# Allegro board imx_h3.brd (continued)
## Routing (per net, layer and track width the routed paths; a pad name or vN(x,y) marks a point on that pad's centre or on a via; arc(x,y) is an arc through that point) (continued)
VBUS_MODEM: length 8.2
  TOP w0.5: C237.1 82.73,13.85 83.13,14.25 83.13,15.87 83.07,15.93 v1(83.07,15.94)
  BOTTOM w0.3: 83.64,12.96 83.65,12.97 83.65,14.3 83.24,14.71 C238.1 ; L24.1 82.59,16.41 83.32,15.68 83.32,15.34
  BOTTOM w0.5: v1(83.07,15.94) 83.06,15.93 83.06,15.6 83.32,15.34 83.32,15.3 C238.1
VBUS_OTG: length 49.7
  TOP w0.1: 84.74,8.47 C236.1 85.91,7.62 ; D4.C 85.22,10.47 ; D4.C 86,9.81 ; D4.C 84.43,9.81 ; C241.1 84.69,6.13 ; C241.1 84.22,6.6 ; C241.1 84.22,5.66
  TOP w0.3: v1(106.34,73.15) 106.32,73.16 R93.2 105.49,73.4 104.9,73.99 104.06,73.99 103.97,74.08 103.97,74.56 C254.1 ; v1(115.6,15.2) L3.1
  TOP w0.5: v1(84.32,5.35) 84.74,5.78 C236.1 85.22,8.1 D4.C
  PWR w0.5: 103.79,42.12 103.79,42.61 101.64,44.75 101.64,46.9 103.11,48.37 103.11,50.81 104.68,52.38 104.68,55.97 104.42,56.22 v1(104.42,62.53)
  BOTTOM w0.5: v1(104.42,62.53) 104.41,62.53 103.62,63.31 103.62,70.66 106.11,73.15 v1(106.34,73.15)
  vias: v1(84.47,4.25) v1(85.14,5.22) v1(85.27,4.27) v1(85.92,5.27) v1(86.02,4.27) v1(120.2,31.22) v1(122.63,31.19)
VBUS_TOP: length 7.9
  TOP w0.1: C240.1 27.52,22.7 27.65,22.82 v1(27.65,23.15)
  TOP w0.3: C234.1 26.35,21.2 C240.1
  BOTTOM w0.3: v1(27.65,23.15) 27.65,23.65 27.35,23.94 26.65,23.94
  BOTTOM w0.5: L21.1 28.8,20.27 28.8,22 v1(27.65,23.15)
VDD1P5_1V5: length 11.9
  TOP w0.5: 64.48,39.52 65.58,39.52 C121.1 ; 64.48,39.52 64.57,39.43 64.57,39.36 64.92,39.02 64.92,38.89 C119.1 65.66,38.76 66.27,38.16 66.27,37.74 C123.1 ; 64.48,39.52 64.41,39.59 v1(64.41,39.64)
  PWR w0.5: v1(64.41,39.64) 64.47,39.64 64.67,39.84 64.67,41.48 64.33,41.81 64.25,41.81 63.65,42.42 63.48,42.42 62.59,43.31 v1(62.59,43.23)
  BOTTOM w0.25: U1.D16 62.59,43.29 v1(62.59,43.23)
  BOTTOM w0.5: C122.1 64.6,39.99 64.6,39.88 64.41,39.69 v1(64.41,39.64) 64.53,39.52 64.63,39.52 C120.1
VDD_1V5: length 6.5
  TOP w0.1: 101.63,82.64 101.63,83.64
  TOP w0.3: 101.63,83.64 101.52,83.75 100.38,83.75 100.23,83.89 100.23,84.94 100.44,85.14 100.92,85.14 101.38,85.61 101.38,86.22 v1(101.46,86.3)
  BOTTOM w0.3: v1(101.46,86.3) 101.39,86.23 101.39,85.52
VDD_4P2: length 19.3
  TOP w0.1: C129.1 65.72,32.75 65.73,32.75 ; C129.1 65.71,32.29 ; C129.1 65.24,32.75
  TOP w0.5: 64.28,33.94 64.28,32.85 C131.1 64.38,32.75 65.73,32.75 ; 64.28,33.94 64.28,33.52 v1(65.06,32.74) ; 64.28,33.94 C132.1 64.3,34.29 64.3,34.72 64.07,34.94 64.07,35.02 63.93,35.16 63.84,35.16 63.53,35.48 C130.1 63.24,35.61 62.68,36.17 v1(61.65,36.17)
  BOTTOM w0.3: 59.84,41.24 59.84,40.27 59.54,39.97 59.54,39.89 59.42,39.77 59.42,38.72 59.84,38.3 59.84,37.53 61.09,36.29 61.52,36.29 v1(61.65,36.17)
  BOTTOM w0.5: v1(65.06,32.74) 68.41,32.74 C133.1
VDD_XTAL: length 56.7
  TOP w0.1: C140.1 58.39,41.47 58.39,41.18 58.22,41.01 58.22,40.45 58.22,40.45 58.22,40.11 58.43,39.9 58.48,39.9 58.82,39.56 58.82,38.88 58.42,38.48 58.42,37.98 58.41,37.97 58.41,33.31 57.98,32.88 57.98,29.86 60.73,27.11 61.7,27.11 61.84,26.96 v1(61.84,26.76) ; v1(69.64,20.32) 69.64,20.34 69.31,20.68 65.34,20.68 65.05,20.38 64.82,20.15 64.8,20.15 63.62,18.97 63.62,3.19 SW2.2
  TOP w0.3: v1(58.66,42.47) 58.66,42.32 58.73,42.25 C140.1
  BOTTOM w0.1: v1(69.64,20.32) 69.55,20.32 68.75,21.12 65.99,21.12 61.84,25.26 v1(61.84,26.76)
  BOTTOM w0.3: v1(58.66,42.47) 58.66,42.47 58.68,42.47 59.05,42.84
ADC_BATT: length 22.7
  TOP w0.1: v1(61.87,43.17) 61.89,43.17 62.23,42.83 63.29,42.83 63.41,42.71 64.2,42.71 64.31,42.81 64.42,42.81 64.58,42.98 64.58,42.99 64.91,43.32 66.43,43.32 66.8,42.94 74.09,42.94 75.48,44.34 76.07,44.34 76.56,43.85 76.56,42.2 75.25,40.89 v1(74.6,40.89)
  BOTTOM w0.1: C153.1 73.53,40.09 R165.2 74.33,40.89 v1(74.6,40.89) ; v1(61.87,43.17) 61.83,43.13 61.81,43.13 61.52,42.84 61.45,42.84
BKGD: length 15
  TOP w0.1: 13.21,57.57 13.21,59.47 13.64,59.9 15.79,59.9 16.69,60.79 16.69,64.56 17.43,65.31 18.98,65.31 v1(19.45,65.78)
  BOTTOM w0.1: v1(19.45,65.78) 19.45,66.98 19.16,67.28 U4.34
BT_ACTIVE: length 116.3
  TOP w0.1: v1(12.87,32.44) 12.93,32.5 J20.41
  INT1 w0.1: v1(12.87,32.44) 12.94,32.51 12.94,40.36 12.96,40.38 12.96,40.97 20.16,48.17 20.16,49.57 21.37,50.78 21.37,51.87 21.36,51.87 21.36,52.21 22.31,53.15 22.82,53.15 23.15,53.15 23.48,53.15 27.39,53.15 28.6,54.37 28.97,54.37 30.31,55.71 30.31,55.71 31.57,56.97 31.91,56.97 32.24,56.97 32.24,56.97 32.91,56.97 32.92,56.96 33.75,56.96 33.77,56.97 34.26,56.97 34.26,56.97 34.84,56.97 34.85,56.96 35.34,56.96 35.91,56.96 36.96,58.01 36.96,64.3 44.75,72.09 45.94,72.09 46.34,72.5 62.85,72.5 71.41,72.5 71.85,72.05 79,72.05 79.45,72.5 80.47,72.5 83.03,75.06 83.03,78.06 84.03,79.06 85.96,79.06 v1(86.05,79.14)
  BOTTOM w0.1: v1(86.05,79.14) 86.6,79.69 86.6,81.39 88.59,83.37 88.59,83.73 88.8,83.94 R101.1
BT_HOST_WAKE: length 86.1
  TOP w0.1: J20.43 14.55,31.7 14.54,31.69 14.52,31.69 14.51,31.7 14.21,31.7 14.2,31.69 v1(12.92,31.69)
  INT1 w0.1: v1(47.75,71.78) 44.72,71.78 37.16,64.22 37.16,57.93 35.99,56.76 35.26,56.76 34.77,56.76 34.76,56.77 34.17,56.77 34.17,56.78 33.85,56.78 33.84,56.76 32.84,56.76 32.83,56.76 32.16,56.76 32.16,56.77 31.66,56.77 30.4,55.51 30.39,55.51 29.05,54.17 28.68,54.17 27.47,52.95 23.4,52.95 22.39,52.95 21.56,52.12 21.56,51.72 21.57,51.72 21.57,50.7 20.36,49.49 20.36,48.09 13.16,40.89 13.16,32.91 13.27,32.79 13.27,32.08 12.92,31.73 v1(12.92,31.69)
  BOTTOM w0.1: U17.13 63.9,65.74 61.71,67.93 61.71,70.19 61.08,70.83 59.71,72.2 59.39,72.2 59.39,72.2 48.52,72.2 48.09,71.78 v1(47.75,71.78)
BT_RESET_B: length 79.2
  TOP w0.1: v1(19.44,38.32) 20.8,36.96 20.8,36.16 22.11,34.85 22.11,32.45 22.46,32.1 J20.42
  INT1 w0.1: v1(45.59,70.79) 45.59,70.75 44.44,69.61 44.44,68.99 43.7,68.26 43.7,67.76 43.7,67.76 43.7,66.67 38.15,61.11 38.15,57.91 37.69,57.46 37.69,57.45 36.41,56.16 36.02,56.16 35.69,56.16 35.36,56.16 35.01,56.16 34.52,56.16 34.51,56.17 34.1,56.17 34.09,56.16 32.58,56.16 32.58,56.16 32.08,56.16 32.08,56.16 31.91,56.16 30.65,54.91 30.64,54.91 29.3,53.56 28.93,53.56 25.96,50.6 25.96,46.32 21.71,42.06 21.71,40.08 19.94,38.32 v1(19.44,38.32)
  BOTTOM w0.1: U17.16 63.41,67.24 62.41,68.24 62.41,70.35 61.88,70.88 61.58,71.18 61.56,71.2 59.96,72.8 59.65,72.8 59.65,72.8 47.37,72.8 47.34,72.81 47.16,72.81 45.59,71.24 v1(45.59,70.79)
BUTTON_1: length 148.3
  TOP w0.1: R151.1 106.13,100.6 R127.1 106.17,100.46 v1(106.17,99.61)
  INT1 w0.1: v1(58.4,25.63) 58.45,25.63 59.65,24.43 60.98,24.43 61.75,23.66 83.15,23.66 83.76,23.06 83.76,23.06 83.87,22.94 88.52,22.94 88.72,23.14 v1(88.72,23.24) ; v1(106.17,99.61) 106.17,99.39 107.23,98.33 107.23,80.88 104.14,77.78 104.14,71.86 102.86,70.59 102.86,62.19 103.59,61.46 103.59,59.16 94.72,50.28 v1(94.72,44.95)
  BOTTOM w0.1: 53.45,42.03 53.42,42.03 53.06,41.68 52.66,41.68 52.15,41.17 52.15,41.11 51.97,40.93 51.97,40.93 50.81,39.78 49.61,39.78 48.72,38.89 48.33,38.89 47.55,38.11 47.55,35.81 48.79,34.56 49.23,34.56 50.74,33.04 51.07,33.04 54.94,29.16 55.64,29.16 58.4,26.4 v1(58.4,25.63) ; v1(88.72,23.24) 88.72,24.57 89.09,24.95 89.09,34.66 91.22,36.78 93.37,36.78 94.13,37.54 94.14,37.54 94.52,37.91 94.52,39.55 96.81,41.83 97,41.83 97.25,42.08 97.25,43.45 95.65,45.05 94.82,45.05 v1(94.72,44.95)
BUTTON_2: length 69.9
  TOP w0.1: v1(52.96,42.43) 52.92,42.43 50.8,40.31 49.32,40.31 48.99,39.97 v1(48.99,39.94) 48.99,39.91 48.28,39.21 R124.1 ; R144.1 88.69,7.97 87.75,8.91 87.75,13.29 83.16,17.88 83.16,18.65 80.51,21.29 64.09,21.29 63.15,20.35 60.67,20.35 53.99,27.03 53.98,27.03 53.74,27.26 53.74,27.28 49.06,31.97 49.06,33.78 49.05,33.79 v1(49.06,33.79)
  BOTTOM w0.1: 53.45,42.84 53.04,42.43 v1(52.96,42.43) ; v1(48.99,39.94) 48.8,39.94 47.63,38.77 47.63,38.76 47.14,38.28 47.14,36.62 47.14,36.61 47.14,36.28 47.14,36.27 47.14,35.8 49.06,33.88 v1(49.06,33.79)
BUTTON_3: length 85.6
  TOP w0.1: v1(42.44,40.48) 42.66,40.71 46.73,40.71 ; v1(53.1,43.24) 53.1,43.21 52.74,42.85 51.49,42.85 50.38,41.74 48.81,41.74 47.77,40.71 46.73,40.71 ; R140.1 46.6,40.58 46.73,40.71 ; v1(97.9,7.7) 98.33,7.27 R153.2
  INT1 w0.1: v1(97.9,7.7) 97.74,7.86 95.06,7.86 94.97,7.94 94.97,7.97 94.82,7.97 94.59,8.2 93.91,8.2 91.84,10.27 91.84,12.12 81.84,22.12 81.73,22.12 69.14,22.12 68.2,23.06 62,23.06 61.99,23.06 61.5,23.06 61.26,23.29 61.26,23.29 60.78,23.77 59.1,23.77 57.33,25.54 57.33,25.78 57.23,25.88 v1(56.1,25.88)
  BOTTOM w0.1: v1(53.1,43.24) 53.11,43.25 53.11,43.3 53.45,43.63 ; v1(42.44,40.48) 42.53,40.39 42.53,38.59 42.69,38.44 42.69,38.43 44,37.11 44,37.02 45.56,35.46 45.56,35.35 46.23,34.69 46.23,34.69 48.16,32.75 48.16,32.75 49.18,31.74 49.55,31.74 49.56,31.75 50.67,31.75 54.29,28.12 54.62,28.12 55.26,27.49 55.26,27.04 56.1,26.19 v1(56.1,25.88)
BUTTON_4: length 66.6
  TOP w0.1: v1(57.09,43.22) 57.09,43.21 57.15,43.15 57.15,42.78 57.15,42.78 57.15,41.6 56.6,41.05 55.79,41.05 54.94,40.2 53.95,40.2 53.32,39.57 v1(53.32,39.44) ; R152.2 92.67,8.72 83.36,18.03 83.36,19 81.65,20.72 81.65,20.74 v1(81.62,20.76) ; 53.92,38.18 v1(53.92,38.41) ; 53.92,38.18 53.09,37.34 53.09,35.49 57.52,31.06 57.52,29.75 61,26.27 62.27,26.27 v1(62.38,26.38) ; 53.92,38.18 53.92,37.71 53.97,37.67 R126.1
  BOTTOM w0.1: v1(62.38,26.38) 62.38,25.01 66.07,21.31 81.07,21.31 v1(81.62,20.76) ; v1(53.32,39.44) 53.92,38.84 v1(53.92,38.41) ; 57.45,43.63 57.45,43.55 57.12,43.22 v1(57.09,43.22)
DCDC_VDDA_1V8: length 166.4
  TOP w0.1: 76.73,49.25 C1.1 ; v1(59.44,42.51) 59.44,42.52 59.33,42.52 59.09,42.76 59.09,43.82 59.1,43.83 59.1,44.46 59.25,44.61 59.25,44.72 60.16,45.63 ; 76.44,56.39 C245.1 76.91,55.92 ; 76.75,48.42 76.75,47.95 76.28,47.95 ; 60.16,45.63 60.16,45.64 ; 60.16,45.63 60.19,45.66 v1(60.23,45.66) ; 76.4,54.24 C78.1 ; 76.52,55.45 C8.1 76.99,55.92 ; 76.99,52.59 C9.1 ; 76.75,46.87 76.75,46.4 76.28,46.4 ; 76.46,51.94 C16.1 76.93,52.4 ; v1(100.05,54.03) 100.16,54.13 J13.17 J13.19 ; 57.06,49.75 57.07,49.75
  TOP w0.3: C111.1 61.55,42.02 61.84,42.31 61.84,42.48 61.85,42.49 v1(61.88,42.49) ; C83.1 59.64,46.25 v1(60.23,45.66) ; v1(75.14,43.05) 75.14,43.12 C4.1 ; C87.1 60.3,52.97 v1(60.22,52.89) ; C9.1 76.33,53.06 76.29,53.09 ; 76.41,50.9 76.68,51.18 C12.1 ; 76.41,50.9 76.41,50.91 76.93,51.44 C16.1 ; 76.41,50.9 v1(76.37,50.87) 76.5,50.87 C11.1 76.77,50.43 76.41,50.07 v1(76.41,49.99) 76.51,49.99 ; C21.1 71.63,49.47 v1(71.63,49.92) ; 75.47,57.31 75.45,57.29 73.98,57.29 73.87,57.41 v1(73.8,57.41) ; v1(98.92,47.66) 99.09,47.66 100.58,49.13 100.63,49.13 J13.1 ; C13.1 v1(68.67,45.86) ; 76.75,46.4 76.66,46.49 76.66,46.84 v1(76.48,47.02) ; C22.1 69.53,51.78 69.12,51.37 69.04,51.37 v1(69.02,51.34) ; C7.1 69.99,43.77 v1(69.99,44.45) ; 58.59,51.14 58.59,50.72 58.73,50.58 ; 58.59,51.14 59.15,50.58 ; 58.59,51.14 C84.1 58.59,51.28 58.55,51.24 58.55,51.23 ; v1(61.05,48.1) 61.2,47.95 C94.1 ; v1(69.02,47.96) 68.37,47.96 C20.1 ; v1(58.59,50.43) 57.86,50.43 v1(57.85,50.44) 57.7,50.44 57.09,49.84 C90.1 ; C1.1 76.59,49.99 76.51,49.99 ; 58.73,50.58 58.65,50.5 57.83,50.5 ; 58.73,50.58 59.15,50.58 ; C10.1 68.34,49.27 68.6,49.01 v1(68.75,49.01) ; C112.1 73.89,40.02 73.89,40.41 73.03,41.27 C113.1 73.05,41.34 ; 57.83,50.5 57.35,50.5 ; 57.83,50.5 57.84,50.52 ; v1(59.44,42.51) 59.44,42.51 59.41,42.49 59.41,41.88 C86.1 ; 59.15,50.58 59.34,50.39 v1(59.41,50.39) 59.44,50.42 ; C89.1 63.08,46.96 v1(62.64,46.52) ; 55.33,44.63 55.16,44.47 55.1,44.47 54.89,44.26 ; 76.29,53.09 77,53.81 C78.1 76.99,54.25 C8.1 ; 76.29,53.09 v1(76.27,53.09) ; C92.1 73.95,42.25 C5.1 73.22,41.5 73.05,41.34 ; C98.1 61.51,51.23 v1(61.1,51.23) ; 76.51,49.99 77.28,49.22 77.28,48.48 76.75,47.95 76.75,47.69 77.07,47.37 v1(77.09,47.37) ; J13.25 101.64,56.12 102.96,56.12 103.16,56.32 103.45,56.32 103.78,55.99 103.78,55.29 103.33,54.84 C264.1 103.13,54.63 J13.19 ; v1(56.25,44.92) 56.18,44.86 55.97,44.86 55.94,44.84 v1(55.53,44.84) 54.89,44.84 C74.1 ; v1(59.36,48.83) 59.9,48.83 60.07,49 C80.1 ; v1(71.78,46.47) 71.78,46.67 71.73,46.72 C19.1 ; C18.1 73.86,50.06 73.49,49.69 73.49,49.65 v1(73.48,49.65) ; C23.1 73.56,46.58 73.56,47.05 v1(73.61,47.09) ; 73.05,41.34 73.05,42.08 73.33,42.35 v1(73.33,42.45) ; C88.1 61.98,52.34 61.5,52.34 61.23,52.06 v1(61.09,52.06) 61.09,52.07 ; 57.06,49.75 57.06,50.21 57.35,50.5 ; 57.35,50.5 57.19,50.5 C81.1 ; C6.1 69.37,55.53 v1(69.56,55.53)
  TOP w0.5: C74.1 55.46,44.91 v1(55.53,44.84) 55.33,44.63 55.24,44.63 54.89,44.28 54.89,44.26 C75.1 ; C76.1 56.19,46.29 ; 56.19,46.29 55.68,46.81 C77.1 ; 56.19,46.29 v1(56.25,46.35) ; v1(56.25,45.63) 56.25,45.63 v1(56.25,44.92) ; v1(61.85,45.6) 62.4,45.6 C79.1 62.6,45.89 62.6,46.48 v1(62.64,46.52) ; v1(77.03,44.72) 80.87,44.72 82.01,45.85 v1(87.96,45.85) ; v1(72,42.44) v1(72.61,42.44) 73.31,42.44 v1(73.33,42.45) ; v1(98.92,47.66) 97.07,45.81 95.28,45.81 94.62,46.47 94.03,46.47 93.63,46.86 93.63,47.07 93.62,47.08 v1(93.62,47.12)
  PWR w0.1: 59.41,42.45 59.41,42.49 59.44,42.51 v1(59.44,42.51)
  PWR w0.3: v1(100.05,54.03) 100.05,48.74 98.97,47.66 v1(98.92,47.66)
  PWR w0.5: v1(61.88,42.49) 61.85,42.51 v1(59.44,42.51)
  BOTTOM w0.1: 75.96,47.71 75.96,48.06 75.61,48.06 ; 58.63,50.39 v1(58.59,50.43) ; 75.96,53.66 76.3,53.66 ; 75.96,53.66 75.96,54 ; 75.96,53.66 75.61,53.66 ; 72.46,57.51 C17.1 71.99,57.98 ; 75.96,45.2 75.96,44.51 ; v1(57.85,55.85) 57.93,55.94 58.13,55.94 58.73,56.53 58.73,57.42 C24.1 58.72,56.51 ; 60.23,45.72 v1(60.23,45.66)
  BOTTOM w0.175: 59.41,46.44 59.47,46.49
  BOTTOM w0.25: U1.G9 57.05,46.44 59.41,46.44 ; U1.G13 59.84,46.11 59.47,46.49 59.47,47.3 59.81,47.63 U1.J13 ; U1.P11 58.64,51.24 58.64,50.67 58.64,50.67 58.64,50.43
  BOTTOM w0.3: 55.84,45.24 56.24,45.63 ; 55.84,45.24 55.93,45.24 56.22,44.94 56.23,44.94 v1(56.25,44.92) 56.33,44.92 56.64,45.24 56.25,45.63 ; 55.84,45.24 55.56,44.96 55.56,44.87 v1(55.53,44.84) ; 56.24,45.63 v1(56.25,45.63) 56.25,45.63 ; 56.24,45.63 U1.G9 56.33,46.35 v1(56.25,46.35) 56.16,46.35 U1.G8 56.25,45.63 ; C17.1 C14.1 ; C14.1 73.78,57.4 73.8,57.41 v1(73.8,57.41) 73.87,57.41 73.98,57.29 C93.1 74.14,57.69 C91.1 73.59,57.98 C14.1 ; v1(73.33,42.45) 73.33,42.35 73.05,42.08 C15.1 ; v1(76.48,47.02) 76.48,46.77 76.17,46.46 ; U2.R1 v1(69.56,55.53) ; v1(62.64,46.52) 62.64,46.44 63.05,46.03 ; v1(69.02,51.34) 69.1,51.25 U2.J1 ; U2.C3 71.17,46.47 v1(71.78,46.47) ; 57.86,50.43 v1(57.85,50.44) ; v1(57.85,50.44) 57.84,50.43 57.84,50.43 57.45,50.03 ; v1(57.85,50.44) 57.85,50.43 U1.M11 58.24,50.08 v1(58.59,50.43) ; 61.54,48.44 61.38,48.44 v1(61.05,48.1) ; 59.13,56.87 60.61,58.35 61,58.35 61.08,58.44 61.08,58.83 C95.1 62.04,59.13 C109.1 C110.1 ; 59.13,56.87 58.76,56.5 R2.1 58.72,56.51 58.77,56.51 59.13,56.87 ; 59.84,42.84 59.82,42.84 59.5,42.51 v1(59.44,42.51) ; v1(61.1,51.23) 61.1,51.18 61.45,50.84 61.45,50.84 ; 76.89,44.85 76.77,44.97 76.42,44.97 76.3,44.85 75.96,44.85 76.31,44.5 76.31,44.4 75.12,43.22 75.12,43.06 v1(75.14,43.05) ; 76.89,44.85 v1(77.03,44.72) ; 76.89,44.85 76.98,44.94 ; v1(61.88,42.49) 61.88,42.4 U1.B16 ; U2.A1 69.96,44.45 v1(69.99,44.45) ; v1(76.41,49.99) 76.29,49.99 75.96,49.66 ; v1(61.09,52.06) 61.45,52.43 61.45,52.44 ; v1(73.61,47.09) 73.61,47.04 74.2,46.46 U2.C7 ; v1(61.85,45.6) 61.84,45.6 61.45,46 61.45,46.03 ; v1(60.23,45.66) 59.85,46.03 U1.G13 ; U1.R13 60.22,52.81 v1(60.22,52.89) ; v1(76.27,53.09) 76.16,53.09 75.96,53.29 75.96,53.66 ; v1(68.67,45.86) 68.84,46.03 68.84,46.03 69.27,46.46 U2.C1 ; v1(68.75,49.01) 68.85,49.1 69,49.1 U2.G1 ; U2.G3 71.36,49.66 71.62,49.92 v1(71.63,49.92) ; 59.84,50.84 59.84,50.82 v1(59.41,50.39) 59.24,50.22 59.24,50.22 59.05,50.03 59.05,50.03 58.64,50.43 ; 59.84,49.24 59.77,49.24 59.37,48.83 v1(59.36,48.83) ; 76.17,46.46 75.96,46.46 ; 76.17,46.46 76.18,46.46 v1(77.09,47.37) 77.07,47.37 76.38,48.06 75.96,48.06 ; U2.G7 73.5,49.66 73.49,49.65 v1(73.48,49.65) ; v1(76.37,50.87) 76.34,50.87 75.96,51.25 ; v1(98.92,47.66) 98.61,47.34 98.61,46.91 98.43,46.74 98.43,46.64 98.04,46.25 C261.1 ; v1(69.02,47.96) 69.12,48.06 U2.E1
  BOTTOM w0.5: v1(93.62,47.12) 93.49,47.25 91.31,47.25 89.91,45.85 v1(87.96,45.85)
DCDC_VDDD_1V2: length 24.6
  TOP w0.3: v1(57.8,44.88) 57.78,44.9 ; v1(67.92,37.96) 67.95,37.93 67.95,37.46 C63.1 68.53,37.44 68.53,37.77 v1(68.72,37.96) ; 58.65,48.06 v1(58.62,48.09) 58.59,48.05 58.03,48.05 C60.1 ; 58.48,45.56 v1(57.86,45.56)
  TOP w0.5: 57.8,44.89 v1(58.55,45.64) 58.55,45.64 58.78,45.87 C62.1 58.21,46.33 C57.1 58.1,45.81 v1(57.86,45.56) 57.8,45.51 57.8,44.89 ; 57.8,44.89 v1(57.8,44.88) 57.62,44.7 C59.1 ; v1(69.51,37.68) 69.53,37.66 69.62,37.66 69.94,37.34 70.6,37.34 C117.1 70.64,37.04 70.24,37.04 70.15,36.96 69.47,36.96 v1(69.4,37.02) ; C114.1 66.65,39.14 C116.1 66.74,38.85 67,38.59 67,38.44 67.14,38.3 67.29,38.3 67.63,37.96 v1(67.92,37.96)
  BOTTOM w0.25: v1(63.44,43.31) 63.37,43.31 63.05,43.63
  BOTTOM w0.3: v1(57.86,45.56) 57.87,45.57 57.87,45.74 58.16,46.03 U1.G11 58.25,46.03 58.55,45.73 v1(58.55,45.64) ; v1(57.86,45.56) 57.92,45.56 58.24,45.24 ; v1(57.86,45.56) 57.86,45.62 57.45,46.03 ; v1(57.86,45.56) 57.86,45.56 57.77,45.56 57.45,45.24 v1(57.8,44.88) 57.89,44.88 58.24,45.24 ; C115.1 67.95,38.56 67.95,38 v1(67.92,37.96) ; 58.24,45.24 58.55,45.54 v1(58.55,45.64) ; v1(58.55,45.64) 58.61,45.64 ; 58.61,45.64 58.65,45.64 59.05,46.03 59.05,46.02 v1(59.43,45.63) 59.05,45.24 59.05,45.24 59.01,45.24 58.61,45.64 ; v1(58.62,48.09) 58.7,48.09 59.05,48.44
  BOTTOM w0.5: C118.1 69.75,37.22 69.55,37.02 v1(69.4,37.02)
DCDC_VDDIO_3V3: length 261.8
  TOP w0.1: v1(100.39,87.71) 98.83,89.27 98.83,96.62 97.49,97.96 R45.2 98.22,99.83 102.82,99.83 103.59,100.6 R151.2 ; v1(92.92,37.62) 92.97,37.57 94.28,37.57 R52.1 ; R53.1 92.86,39.46 92.43,39.03 91.07,39.03 91.04,39 91.04,38.97 v1(91.04,38.97) ; v1(54.45,39.34) 54.3,39.18 54.3,38.62 54.98,37.94 54.98,37.47 ; v1(63.39,69.45) 63.41,69.47 63.41,69.52 64.09,70.19 64.59,70.19 65.19,70.79 65.19,71.51 v1(65.17,71.52) ; v1(48.62,47.97) 48.53,48.06 47.38,48.06 47.37,48.05 R17.1 ; 63.35,50.78 C96.1 63.82,50.31 ; 47.06,39.64 R124.2 46.86,39.21 46.53,39.54 ; 47.06,39.64 R140.2 ; 47.06,39.64 46.96,39.54 46.53,39.54 ; v1(99.69,61.13) J13.45 J13.47 ; v1(99.82,62.62) 100.31,62.13 J13.49 J13.47 ; v1(85.65,60.95) 85.65,62.05 87.2,63.6 v1(87.2,68.1) 87.2,69.7 87.71,70.21 v1(87.71,70.47) 87.83,70.47 87.84,70.49 R118.1 ; J20.1 15.45,51.81 C217.1 ; v1(99.59,61.91) 99.93,61.91 100.2,61.63 J13.47 ; v1(98.86,27.92) 98.86,29.31 97.99,30.18 97.99,38.72 96.5,40.21 95.77,40.21 v1(95.32,39.76) ; v1(95.11,42.91) 95.23,42.8 95.25,42.8 95.57,42.48 R51.1 ; v1(40.19,69.75) 39.74,70.19 R66.2 ; 62.68,41.51 62.74,41.51 62.78,41.56 ; v1(52.34,38.46) 51.64,37.75 51.64,37.61 51.59,37.61 ; v1(89.37,44.15) 89.39,44.15 89.54,44 R54.1 89.54,42.22 R55.1 89.5,40.91 R56.1 ; 46.53,39.54 46.42,39.54 46.42,39.59 46.46,39.59 46.46,39.54 v1(46.45,39.54)
  TOP w0.3: 56.3,48.01 C72.1 57,48.02 ; 56.3,48.01 v1(56.29,47.99) 55.69,47.99 55.64,48.05 C65.1 ; 56.3,48.01 56.31,48.02 57,48.02 ; v1(56.33,47.23) 55.94,47.62 55.06,47.62 C64.1 ; 98.94,46.53 100.41,48 103.27,48 103.35,48.09 ; v1(15.21,52.36) 15.55,52.02 J20.1 ; 103.35,48.09 C260.1 ; 103.35,48.09 103.41,48.09 103.41,48.44 103.12,48.73 103.12,51.33 C255.1 103.38,51.58 102.94,51.13 J13.5 ; 57,48.02 v1(57.03,48.02) ; C71.1 52.04,51.18 52.01,51.21 51.53,51.21 v1(51.44,51.3) ; v1(51.46,46.49) 51.12,46.84 C67.1 ; v1(22.06,35.52) 22.12,35.52 22.7,36.1 J20.32 ; C66.1 52.68,44.03 53.05,44.03 v1(53.07,44.05) ; v1(63.83,50.84) 63.36,50.36 63.29,50.36 ; C100.1 65.75,42.31 C69.1 64.94,42.85 v1(64.5,42.42) 64.49,42.42 64.31,42.25 63.14,42.25 62.78,41.88 62.78,41.49 C101.1 ; C70.1 55.2,39.34 v1(54.45,39.34)
  TOP w0.5: v1(41.95,61.6) 42.07,61.72 C103.1
  INT1 w0.1: v1(100.39,87.71) 100.39,87.34 96.26,83.21 96.26,82.88 96.27,82.88 96.27,76.73 96.26,76.73 96.26,76.39 96.27,76.39 96.27,72.33 93.34,69.41 93.34,69 92.98,68.64 92.94,68.64 92.15,67.85 87.45,67.85 v1(87.2,68.1) ; v1(87.71,70.47) 86.31,70.47 82.08,66.25 82.08,66.21 81.46,65.59 v1(81.46,65.27)
  PWR w0.1: v1(55.7,55.81) 55.7,55.8 55.94,55.8 56.24,56.09
  PWR w0.5: 17.28,48.29 17.07,48.5 17.07,49.04 17.07,49.05 17.06,49.07 17.05,49.08 v1(17.04,49.08)
  BOTTOM w0.1: P2.1 91.31,43.43 90.92,43.82 90.92,43.86 90.76,44.01 90.57,44.01 v1(90.43,44.15) ; R134.2 95.02,39.45 95.32,39.75 v1(95.32,39.76) ; U31.5 23.59,28.79 22.7,29.69 21.95,29.69 21.75,29.49 v1(21.75,29.4) ; R26.1 35.17,62.32 35.2,62.35 35.2,63.41 35.11,63.5 R25.1 35.88,64.41 C52.1 ; v1(63.39,69.45) 63.41,69.47 63.41,69.52 63.78,69.9 R104.1 63.76,69.97 R105.1 ; U1.E16 v1(61.91,44.1) ; 65.76,41.71 C99.1 65.76,42.65 ; U40.14 17.13,33.95 17.51,33.58 v1(17.55,33.58) ; R213.2 103.28,17.13 100.98,19.43 100.98,25.86 99.06,27.78 99,27.78 v1(98.86,27.92) ; R109.1 64.54,72.15 v1(65.17,71.52)
  BOTTOM w0.15: 64.62,41.34 64.62,43.23 64.27,43.58 64.27,43.67 63.98,43.96 62.72,43.96 U1.E16
  BOTTOM w0.25: 63.05,42.84 63.05,42.76 63.21,42.6 ; U1.E6 54.24,44.43 53.84,44.03 53.1,44.03 v1(53.07,44.05) ; 63.21,42.6 63.89,41.91 63.89,41.19 64.03,41.06 64.03,40.6 64.03,40.59 v1(64.03,40.45) 64.03,40.45 ; 63.21,42.6 64.33,42.6 64.5,42.42 v1(64.5,42.42)
  BOTTOM w0.3: 57.45,47.63 57.45,47.7 57.12,48.02 v1(57.03,48.02) 56.65,47.63 U1.J9 ; C266.1 60.68,64.04 C51.1 59.56,64.04 59.07,64.53 U5.37 56.03,64.53 v1(55.83,64.32) ; v1(46.82,52.5) 46.84,52.5 47.47,51.88 C97.1 ; v1(64.87,69.2) 64.68,69.02 64.68,68.48 U17.18 ; v1(15.21,52.36) 15.21,51.49 15.89,50.81 15.91,50.81 16,50.73 16,50.6 16.31,50.29 C102.1 ; 21.89,34.49 21.89,35.29 22.11,35.5 22.11,35.52 v1(22.06,35.52) ; v1(63.77,39.9) 64,40.12 64,40.56 64.03,40.58 ; C187.1 66.65,69.88 66.49,69.72 66.49,69.69 v1(66.49,69.69) 66.63,69.54 U17.21 ; v1(51.44,51.3) 51.44,51.24 51.85,50.82 51.86,50.82 51.87,50.83 ; U1.G3 51.84,46.03 51.46,46.41 v1(51.46,46.49) ; U1.J9 v1(56.29,47.99) 55.93,47.63 U1.J8 56.25,47.23 v1(56.33,47.23) ; U1.J9 55.84,46.84 ; v1(40.03,64.53) U5.12 38.16,64.49 C52.1 35.05,64.49 C265.1 ; U17.24 68.93,68.95 68.94,68.94 69.42,68.94 69.59,68.76 69.59,68.72 v1(69.59,68.72) ; 63.05,50.84 63.83,50.84 v1(63.83,50.84) ; 64.62,41.63 64.85,41.63 64.85,41.63 65.27,41.63 65.56,41.93 65.56,41.98 C99.1
  BOTTOM w0.5: C73.1 17.52,47.88 v1(17.46,47.82) ; 47.24,54.07 47.24,54.07 47.24,53.15 ; 47.24,54.07 v1(47.25,54.07) ; 47.24,54.07 47.24,54.16 46.84,54.55 ; 46.84,54.55 46.84,55.39 46.31,55.93 40.33,55.93 38.98,54.57 38.98,53.62 37.87,52.52 37.87,52.51 36.87,51.51 33.38,51.51 32.6,50.74 28.81,50.74 27.81,49.74 v1(27.81,48.25) ; 46.84,54.55 46.84,53.63 ; 47.24,53.15 46.84,53.54 46.84,53.63 ; 47.24,53.15 47.24,53.14 47.24,53.14 47.24,53.15 v1(47.23,53.15) ; v1(17.04,49.08) 17.04,49.3 C102.1 ; v1(86.21,57.75) 86.25,57.75 88.95,60.45 90.3,60.45 92.2,62.35 99.14,62.35 v1(99.59,61.91) ; v1(46.82,53.6) 46.84,53.63 ; v1(95.11,42.91) 95.15,42.91 95.84,43.6 v1(96.45,43.6) ; v1(27.81,48.25) v1(27.81,47.57) 27.79,47.56 v1(27.15,47.56) v1(27.15,48.24) 27.16,48.25 v1(27.81,48.25) ; v1(54.45,39.34) 54.57,39.45 54.57,40.56 54.95,40.94 54.95,40.95 55.05,41.04 55.05,41.24
  vias: v1(52.34,60.32) v1(53.16,59.58) v1(64.19,59.82)
DDR2_A0: length 20.2
  INT1 w0.12: 65.48,54.78 65.61,54.91 66.66,54.91 66.79,54.78 67.31,54.78 67.88,54.21 68.33,54.21 68.9,53.63 arc(68.94,53.6) 68.98,53.6 69.15,53.6 arc(69.23,53.63) 69.26,53.71 69.26,54.05 arc(69.37,54.16) 69.48,54.05 69.48,53.71 arc(69.59,53.6) 69.7,53.71 69.7,54.06 arc(69.81,54.17) 69.92,54.06 69.92,53.71 arc(70.03,53.6) 70.14,53.71 70.14,54.04 arc(70.25,54.16) 70.36,54.04 70.36,53.71 arc(70.47,53.6) 70.58,53.71 70.58,54.02 arc(70.69,54.13) 70.8,54.02 70.8,53.71 arc(70.91,53.6) 71.02,53.71 71.02,54.01 arc(71.13,54.12) 71.24,54.01 71.24,53.71 arc(71.28,53.63) 71.35,53.6 72.26,53.6 73.14,54.48 v1(73.14,54.5)
  INT1 w0.154: 65.48,54.78 65.28,54.78 65.12,54.93 64.51,54.93 v1(64.51,54.93)
  BOTTOM w0.12: v1(64.51,54.93) 64.51,54.93 64.31,55.13 62.54,55.13 61.45,54.03 ; v1(73.14,54.5) 73.79,54.5 74.2,54.09 74.72,54.09 U2.M8
DDR2_A1: length 20.1
  BOTTOM w0.12: 59.05,54.03 59.05,54.2 61.16,56.31 arc(61.21,56.34) 61.27,56.35 61.3,56.35 arc(61.34,56.35) 61.38,56.32 61.38,56.32 arc(61.4,56.29) 61.41,56.25 61.41,56.18 arc(61.45,56.08) 61.55,56.04 61.55,56.04 arc(61.64,56.08) 61.68,56.17 61.68,56.25 arc(61.69,56.29) 61.71,56.32 61.82,56.44 65.75,56.44 67.63,54.56 67.97,54.56 68.42,54.1 71.28,54.1 71.28,54.09 71.78,53.6 72.87,53.6 arc(73.1,53.37) 72.87,53.15 71.36,53.15 71.3,53.21 70.99,53.21 70.72,53.47 70.72,53.56 70.82,53.66 U2.M3
DDR2_A2: length 20.3
  INT1 w0.12: v1(73.68,53.97) 73.83,54.12 75.2,54.12 arc(75.48,53.84) 75.2,53.56 73.47,53.56 73.34,53.69 72.87,53.69 72.56,53.38 72.56,53.38 68.84,53.38 68.23,53.99 67.79,53.99 67.53,54.25 66.73,54.25 v1(66.61,54.37)
  BOTTOM w0.12: U2.M7 73.98,53.66 73.67,53.97 v1(73.68,53.97) ; v1(66.61,54.37) 66.42,54.37 66.13,54.07 65.58,54.07 65.45,54.2 65.45,54.91 65.02,55.35 62.37,55.35 61.8,54.78 60.89,54.78 60.64,54.53 U1.U14
DDR2_A3: length 20.6
  BOTTOM w0.12: 58.24,53.24 58.24,53.37 58.73,53.86 58.73,54.19 61.08,56.54 arc(61.12,56.57) 61.16,56.57 61.4,56.57 arc(61.48,56.61) 61.51,56.69 61.51,56.92 arc(61.62,57.03) 61.73,56.92 61.73,56.76 arc(61.84,56.66) 61.95,56.76 61.95,56.97 arc(62.06,57.08) 62.17,56.97 62.17,56.76 arc(62.28,56.66) 62.39,56.76 62.39,56.97 arc(62.5,57.08) 62.61,56.97 62.61,56.77 arc(62.72,56.66) 62.83,56.77 62.83,56.97 arc(62.94,57.08) 63.05,56.97 63.05,56.76 arc(63.16,56.66) 63.27,56.76 63.27,56.97 arc(63.38,57.08) 63.49,56.97 63.49,56.76 arc(63.6,56.66) 63.71,56.76 63.71,56.97 arc(63.82,57.08) 63.93,56.97 63.93,56.76 arc(64.04,56.66) 64.15,56.76 64.15,56.97 arc(64.26,57.08) 64.37,56.97 64.37,56.76 arc(64.48,56.66) 64.59,56.76 64.59,56.97 arc(64.7,57.08) 64.81,56.97 64.81,56.76 arc(64.92,56.66) 65.03,56.76 65.03,56.97 arc(65.14,57.08) 65.25,56.97 65.25,56.69 65.26,56.66 65.85,56.66 67.06,55.44 68.7,55.44 69.33,54.81 69.99,54.81 70.12,54.68 70.12,54.68 U2.N2
DDR2_A4: length 21.4
  INT1 w0.12: v1(72.16,56.63) 72.17,56.62 72.17,56.5 72.72,55.95 arc(72.8,55.92) 72.87,55.95 73.02,56.09 arc(73.17,56.09) 73.17,55.94 73.03,55.8 arc(73,55.72) 73.03,55.64 73.28,55.4 v1(73.43,55.4)
  BOTTOM w0.12: 57.45,54.03 57.45,54.16 61.03,57.74 61.36,57.74 61.55,57.74 70.71,57.74 70.96,57.5 71.32,57.5 71.49,57.33 71.49,57.3 v1(72.16,56.63) ; U2.N8 74.93,54.68 74.92,54.68 74.7,54.9 74.21,54.9 73.72,55.39 73.43,55.39 v1(73.43,55.4)
DDR2_A5: length 20.7
  INT1 w0.12: v1(58.66,52.87) 58.66,53.12 59.54,54 59.54,54.84 60.94,56.25 61.52,56.25 arc(61.58,56.22) 61.61,56.16 arc(61.64,56.09) 61.7,56.06 61.74,56.06 arc(61.8,56.09) 61.83,56.16 arc(61.86,56.22) 61.92,56.25 61.96,56.25 arc(62.02,56.22) 62.05,56.16 arc(62.08,56.09) 62.14,56.06 62.18,56.06 arc(62.24,56.09) 62.27,56.16 arc(62.3,56.22) 62.36,56.25 62.4,56.25 arc(62.46,56.22) 62.49,56.16 arc(62.52,56.09) 62.58,56.06 62.62,56.06 arc(62.68,56.09) 62.71,56.16 arc(62.74,56.22) 62.8,56.25 62.84,56.25 arc(62.9,56.22) 62.93,56.16 arc(62.96,56.09) 63.02,56.06 63.06,56.06 arc(63.12,56.09) 63.15,56.16 arc(63.18,56.22) 63.24,56.25 63.28,56.25 arc(63.34,56.22) 63.37,56.16 arc(63.4,56.09) 63.46,56.06 63.5,56.06 arc(63.56,56.09) 63.59,56.16 arc(63.62,56.22) 63.68,56.25 63.72,56.25 arc(63.78,56.22) 63.81,56.16 arc(63.84,56.09) 63.9,56.06 63.94,56.06 arc(64,56.09) 64.03,56.16 arc(64.06,56.22) 64.12,56.25 64.16,56.25 arc(64.22,56.22) 64.25,56.16 arc(64.28,56.09) 64.34,56.06 64.38,56.06 arc(64.44,56.09) 64.47,56.16 arc(64.5,56.22) 64.56,56.25 64.6,56.25 arc(64.66,56.22) 64.69,56.16 arc(64.72,56.09) 64.78,56.06 64.82,56.06 arc(64.88,56.09) 64.91,56.16 arc(64.94,56.22) 65,56.25 65.92,56.25 66.29,55.88 v1(67.27,55.88)
  BOTTOM w0.12: v1(67.27,55.88) 67.32,55.88 67.53,56.08 67.94,56.08 arc(68.01,56.05) 68.05,55.97 68.05,55.78 arc(68.16,55.67) 68.27,55.78 68.27,55.97 arc(68.38,56.08) 68.48,55.97 68.48,55.78 arc(68.59,55.67) 68.7,55.78 68.7,55.97 arc(68.74,56.05) 68.81,56.08 69.03,56.08 69.12,55.99 69.12,55.35 69.44,55.04 70.07,55.04 70.21,54.9 71.4,54.9 71.67,54.63 71.67,54.42 71.58,54.32 71.28,54.32 U2.N3 ; v1(58.66,52.87) 58.66,52.84 58.27,52.44 U1.R11
DDR2_A6: length 20.9
  INT1 w0.12: v1(71.78,55.46) 70.97,55.46 69.7,56.72 60.76,56.72 58.02,53.98 58.02,53.09 v1(57.81,52.88)
  BOTTOM w0.12: v1(71.78,55.46) 72.38,55.46 72.55,55.28 72.64,55.28 72.98,54.94 73.73,54.94 74.22,54.46 U2.N7 ; v1(57.81,52.88) 57.8,52.88 57.74,52.82 57.13,52.82 56.75,52.44 U1.R9
DDR2_A7: length 20.2
  INT1 w0.12: v1(57.84,51.23) 57.84,51.37 58.24,51.76 58.24,53.09 arc(58.25,53.13) 58.27,53.17 58.44,53.34 arc(58.47,53.42) 58.44,53.49 58.28,53.65 arc(58.28,53.81) 58.44,53.81 58.66,53.59 arc(58.81,53.59) 58.81,53.75 58.53,54.03 arc(58.53,54.18) 58.69,54.18 58.95,53.92 arc(59.13,53.92) 59.13,54.1 58.9,54.34 58.89,54.34 arc(58.89,54.49) 59.04,54.49 59.11,54.42 arc(59.17,54.39) 59.24,54.42 arc(59.26,54.45) 59.27,54.49 59.27,54.92 60.83,56.48 66.64,56.48 v1(66.81,56.31)
  BOTTOM w0.12: U2.P2 69.97,55.64 69.97,55.71 69.91,55.77 69.91,55.91 69.91,56.46 69.73,56.64 69.25,56.64 68.91,56.31 v1(66.81,56.31) ; 58.24,50.84 58.24,50.84 v1(57.84,51.23)
DDR2_A8: length 21
  INT1 w0.12: v1(57.25,54.95) 57.29,54.95 57.34,55 57.64,55 60.02,57.38 72.08,57.38 72.82,56.65 v1(72.83,56.65)
  BOTTOM w0.12: U2.P8 74.93,55.48 74.71,55.7 74.21,55.7 74,55.91 74,55.92 73.28,56.65 v1(72.83,56.65) ; v1(57.25,54.95) 57.25,54.87 56.64,54.26 U1.U9
DDR2_A9: length 21.4
  INT1 w0.12: v1(57.82,52.01) 57.82,52.28 57.39,52.71 57.39,53.67 57.8,54.07 58.66,54.93 60.67,56.94 69.8,56.94 70.86,55.88 72.09,55.88 72.31,55.66 72.31,54.87 v1(72.24,54.79)
  BOTTOM w0.12: U2.P3 71.39,55.25 71.93,54.71 72.16,54.71 v1(72.24,54.79) ; 57.45,51.63 v1(57.82,52.01)
DDR2_A10: length 20
  BOTTOM w0.12: U1.U13 59.84,54.36 60.71,55.22 61.57,55.22 arc(61.61,55.23) 61.65,55.25 61.75,55.35 arc(61.77,55.39) 61.78,55.43 61.78,55.44 arc(61.8,55.47) 61.81,55.5 61.81,55.67 arc(61.82,55.71) 61.84,55.75 61.85,55.76 arc(61.89,55.78) 61.93,55.79 62.1,55.79 arc(62.18,55.82) 62.21,55.9 62.21,56.1 arc(62.32,56.22) 62.43,56.1 62.43,55.9 arc(62.55,55.79) 62.66,55.9 62.66,56.1 arc(62.77,56.22) 62.88,56.1 62.88,55.9 arc(62.98,55.79) 63.09,55.9 63.09,56.09 arc(63.2,56.21) 63.31,56.09 63.31,55.9 arc(63.42,55.79) 63.53,55.9 63.53,56.1 arc(63.64,56.22) 63.75,56.1 63.75,55.9 arc(63.87,55.79) 63.98,55.9 63.98,56.1 arc(64.09,56.22) 64.2,56.1 64.2,55.9 arc(64.31,55.79) 64.42,55.9 64.42,56.1 arc(64.53,56.22) 64.64,56.1 64.64,55.9 arc(64.75,55.79) 64.86,55.9 64.86,56.1 arc(64.97,56.22) 65.08,56.1 65.08,55.9 arc(65.19,55.79) 65.3,55.9 65.3,56.1 arc(65.41,56.22) 65.52,56.1 65.52,56.03 arc(65.54,55.98) 65.59,55.96 65.91,55.96 66.18,55.69 66.19,55.69 67.48,54.41 67.54,54.34 67.85,54.34 68.32,53.87 68.41,53.87 arc(68.49,53.84) 68.52,53.76 68.52,53.41 arc(68.63,53.3) 68.74,53.41 68.74,53.76 arc(68.78,53.84) 68.85,53.87 69.07,53.87 arc(69.15,53.84) 69.18,53.76 69.18,53.54 arc(69.29,53.44) 69.4,53.54 69.4,53.76 arc(69.51,53.87) 69.62,53.76 69.62,53.54 arc(69.73,53.44) 69.84,53.54 69.84,53.76 arc(69.88,53.84) 69.95,53.87 70.15,53.87 70.15,53.86 U2.M2
DDR2_A11: length 20.5
  BOTTOM w0.12: U2.P7 74.12,55.48 73.46,56.15 arc(73.42,56.17) 73.38,56.18 73.09,56.18 arc(73.01,56.15) 72.98,56.07 72.98,55.93 arc(72.87,55.81) 72.76,55.93 72.76,56.07 arc(72.72,56.15) 72.65,56.18 71.96,56.18 70.73,57.41 67.29,57.41 67.18,57.52 61.55,57.52 61.44,57.52 61.44,57.52 61.18,57.52 57.8,54.16 57.8,53.6 57.45,53.24 57.45,53.24
DDR2_A12: length 20.4
  BOTTOM w0.12: U1.U11 58.47,54.26 arc(58.49,54.31) 58.47,54.37 58.47,54.37 arc(58.44,54.43) 58.47,54.48 58.51,54.52 arc(58.57,54.55) 58.62,54.52 58.62,54.52 arc(58.68,54.5) 58.74,54.52 58.78,54.57 arc(58.8,54.62) 58.78,54.68 58.78,54.68 arc(58.76,54.74) 58.78,54.79 58.82,54.83 arc(58.88,54.86) 58.93,54.83 58.94,54.83 arc(58.99,54.81) 59.05,54.83 59.09,54.88 arc(59.11,54.93) 59.09,54.99 59.09,54.99 arc(59.07,55.05) 59.09,55.1 59.13,55.15 arc(59.19,55.17) 59.25,55.14 59.25,55.14 arc(59.3,55.12) 59.36,55.14 61.53,57.3 66.72,57.3 67.16,56.86 arc(67.24,56.83) 67.27,56.75 67.27,56.63 arc(67.38,56.53) 67.49,56.63 67.49,57.07 arc(67.6,57.19) 67.71,57.07 67.71,56.63 arc(67.82,56.53) 67.93,56.63 67.93,57.07 arc(68.04,57.19) 68.15,57.07 68.15,56.63 arc(68.26,56.53) 68.37,56.63 68.37,57.07 arc(68.48,57.19) 68.59,57.07 68.59,56.63 arc(68.7,56.53) 68.81,56.63 68.81,56.75 arc(68.85,56.83) 68.92,56.86 70.09,56.86 70.8,56.14 70.8,55.91 70.84,55.87 70.84,55.72 70.73,55.6 70.5,55.6 70.5,55.61 70.34,55.61 70.19,55.75 70.19,55.89 U2.R2
DDR2_A13: length 21.6
  BOTTOM w0.12: U2.R8 75.18,56.06 75.15,56.03 74.88,56.03 74.31,56.6 73.76,56.6 73.17,57.18 72.21,57.18 71.87,57.52 71.67,57.72 71.05,57.72 70.8,57.96 61.55,57.96 60.88,57.96 58.68,55.75 58.68,55.75 57.12,54.19 57.12,53.71 56.64,53.24
DDR2_A14: length 20.2
  INT1 w0.12: v1(70.89,56.66) 70.39,57.16 60.36,57.16 58.77,55.57 arc(58.75,55.52) 58.77,55.46 arc(58.79,55.41) 58.77,55.35 58.72,55.31 arc(58.67,55.29) 58.61,55.31 arc(58.56,55.33) 58.5,55.31 58.46,55.26 arc(58.43,55.21) 58.46,55.15 arc(58.48,55.1) 58.46,55.04 58.41,55 arc(58.36,54.97) 58.3,55 arc(58.25,55.02) 58.19,55 58.15,54.95 arc(58.12,54.9) 58.15,54.84 arc(58.17,54.79) 58.15,54.73 58.1,54.69 arc(58.04,54.66) 57.99,54.69 arc(57.94,54.71) 57.88,54.69 57.83,54.64 arc(57.81,54.59) 57.83,54.53 arc(57.86,54.48) 57.83,54.42 57.79,54.37 arc(57.73,54.35) 57.68,54.37 57.68,54.37 arc(57.62,54.4) 57.57,54.37 57.52,54.33 arc(57.5,54.27) 57.52,54.22 arc(57.55,54.16) 57.52,54.11 57.48,54.06 arc(57.42,54.04) 57.37,54.06 arc(57.31,54.09) 57.26,54.06 57.1,53.91 57.1,51.27 57.13,51.24 v1(57.13,51.24)
  BOTTOM w0.12: v1(57.13,51.24) 57.13,51.23 57.13,51.15 57.45,50.84 ; v1(70.89,56.66) 71.16,56.4 U2.R3
DDR2_BA0: length 15.9
  INT1 w0.12: v1(67.28,52.7) 66.96,52.7 66.67,52.41 66.04,52.41 65.65,52.02 65.31,52.02 64.94,52.39 64.82,52.39 64.72,52.5 64.72,52.84 64.88,52.84 64.99,52.95 65.13,52.95 65.26,53.09 65.26,53.59 65.27,53.59 65.27,53.6 65.2,53.66 64.77,53.66 64.44,53.99 64.43,53.99 63.86,54.57 arc(63.75,54.61) 63.65,54.57 arc(63.6,54.46) 63.65,54.35 64.32,53.68 64.32,53.61 v1(64.11,53.4)
  BOTTOM w0.12: U2.L2 70.45,52.85 arc(70.54,52.84) 70.61,52.79 70.63,52.77 arc(70.66,52.72) 70.67,52.67 arc(70.66,52.61) 70.63,52.56 arc(70.51,52.48) 70.37,52.46 69.03,52.46 arc(68.97,52.48) 68.95,52.54 arc(68.92,52.61) 68.86,52.63 68.81,52.63 arc(68.75,52.61) 68.73,52.54 arc(68.7,52.48) 68.64,52.46 68.59,52.46 arc(68.53,52.48) 68.5,52.54 arc(68.48,52.61) 68.42,52.63 68.38,52.63 arc(68.31,52.61) 68.28,52.54 arc(68.26,52.48) 68.2,52.46 68.16,52.46 arc(68.09,52.48) 68.06,52.54 arc(68.04,52.61) 67.98,52.63 67.94,52.63 arc(67.87,52.61) 67.84,52.54 arc(67.82,52.48) 67.75,52.46 67.65,52.46 67.41,52.7 v1(67.28,52.7) ; 62.24,53.24 62.11,53.1 62.11,53.03 62.1,52.86 62.13,52.83 62.3,52.83 62.55,53.08 62.66,53.08 62.73,53.16 62.73,53.39 62.88,53.55 63.17,53.55 63.52,53.21 63.81,53.21 63.96,53.36 64.07,53.36 v1(64.11,53.4)
DDR2_BA1: length 15.1
  INT1 w0.12: v1(65.73,55.54) 65.59,55.54 65.5,55.63 v1(61.39,55.63)
  BOTTOM w0.12: 59.05,53.24 59.05,53.43 59.43,53.82 59.43,54.26 60.81,55.63 v1(61.39,55.63) ; U2.L3 70.98,52.85 70.62,53.22 69.37,53.22 69.23,53.08 68.28,53.08 68.19,53.17 68.19,53.67 67.74,54.12 67.68,54.12 67.45,54.12 67.32,54.25 66.21,55.36 65.88,55.36 65.7,55.54 v1(65.73,55.54)
DDR2_BA2: length 15.9
  INT1 w0.12: v1(59.45,52.06) 59.45,52.09 59.74,52.38 60.3,52.38 60.42,52.51 61.23,52.51 61.83,53.1 62.05,53.1 arc(62.13,53.13) 62.16,53.21 62.16,53.81 arc(62.27,53.91) 62.38,53.81 62.38,53.21 arc(62.49,53.1) 62.6,53.21 62.6,53.79 arc(62.71,53.9) 62.82,53.79 62.82,53.21 arc(62.85,53.13) 62.93,53.1 63.42,53.1 63.74,52.78 v1(64.03,52.78)
  BOTTOM w0.12: v1(64.03,52.78) 64.79,52.78 64.85,52.84 64.88,52.84 65.12,53.08 65.12,53.11 65.64,53.63 66.36,53.63 66.39,53.67 66.95,53.67 67.76,52.85 U2.L1 ; 59.05,50.84 59.34,50.84 59.49,50.99 59.49,52 v1(59.45,52.06)
DDR2_CAS_B: length 15.3
  INT1 w0.12: v1(73.48,53.13) 73.47,53.15 72.28,53.15 arc(72.21,53.12) 72.18,53.05 arc(72.15,52.98) 72.08,52.95 72.06,52.95 arc(71.99,52.98) 71.96,53.05 arc(71.93,53.12) 71.86,53.15 71.84,53.15 arc(71.77,53.12) 71.74,53.05 arc(71.71,52.98) 71.64,52.95 71.62,52.95 arc(71.55,52.98) 71.52,53.05 arc(71.49,53.12) 71.42,53.15 71.4,53.15 arc(71.33,53.12) 71.3,53.05 arc(71.27,52.98) 71.2,52.95 71.18,52.95 arc(71.11,52.98) 71.08,53.05 arc(71.05,53.12) 70.98,53.15 70.96,53.15 arc(70.89,53.12) 70.86,53.05 arc(70.83,52.98) 70.76,52.95 70.74,52.95 arc(70.67,52.98) 70.64,53.05 arc(70.61,53.12) 70.54,53.15 70.52,53.15 arc(70.45,53.12) 70.42,53.05 arc(70.39,52.98) 70.32,52.95 70.3,52.95 arc(70.23,52.98) 70.2,53.05 arc(70.17,53.12) 70.1,53.15 70.08,53.15 arc(70.01,53.12) 69.98,53.05 arc(69.95,52.98) 69.88,52.95 69.86,52.95 arc(69.79,52.98) 69.76,53.05 arc(69.73,53.12) 69.66,53.15 69.64,53.15 arc(69.57,53.12) 69.54,53.05 arc(69.51,52.98) 69.44,52.95 69.42,52.95 arc(69.35,52.98) 69.32,53.05 arc(69.29,53.12) 69.22,53.15 69.2,53.15 arc(69.13,53.12) 69.1,53.05 arc(69.07,52.98) 69,52.95 68.98,52.95 arc(68.91,52.98) 68.88,53.05 arc(68.85,53.12) 68.78,53.15 68.76,53.15 arc(68.69,53.12) 68.66,53.05 arc(68.63,52.98) 68.56,52.95 68.54,52.95 arc(68.47,52.98) 68.44,53.05 arc(68.41,53.12) 68.34,53.15 68.09,53.15 v1(67.75,53.5)
  BOTTOM w0.12: U2.L7 74.28,52.85 74.19,52.96 73.67,52.96 v1(73.48,53.13) ; v1(67.75,53.5) 67.69,53.5 67.28,53.9 67.07,53.9 67.05,53.88 67.04,53.89 66.29,53.89 66.26,53.85 65.2,53.85 65.1,53.75 65.09,53.75 64.79,53.75 64.79,53.75 64.75,53.75 64.51,53.99 64.51,54.03 63.96,54.58 62.78,54.58 62.24,54.04 U1.U16
DDR2_CKE: length 18.5
  TOP w0.12: R58.1 63.25,54.74 63.36,54.84 64,54.84 64.33,54.52 64.69,54.52 64.77,54.6 65.11,54.6 65.22,54.49 v1(65.88,54.49)
  INT1 w0.12: v1(66.56,53.25) 66.56,53.24 66.59,53.26 66.59,53.77 arc(66.53,53.91) 66.39,53.97 66.31,53.97 arc(66.23,53.93) 66.2,53.85 66.2,53.74 arc(66.04,53.68) 65.89,53.74 arc(65.82,53.9) 65.89,54.05 arc(65.96,54.08) 65.98,54.15 65.98,54.34 65.88,54.44 v1(65.88,54.49)
  BOTTOM w0.12: v1(65.88,54.49) 65.88,54.81 65.12,55.57 62.28,55.57 61.71,55 60.8,55 60.3,54.5 60.3,53.56 59.98,53.24 59.84,53.24 ; U2.K2 70.2,52.21 67.03,52.21 66.6,52.63 66.6,53.17 66.52,53.25 v1(66.56,53.25)
DDR2_CLK: length 14.8
  TOP w0.12: R1.1 73.77,50.98 73.65,51.1 73.44,51.1 73.17,50.83 v1(73.09,50.83)
  INT1 w0.12: v1(73.09,50.83) 73.06,50.8 72.75,50.8 72.31,50.37 71.17,50.37 71,50.2 67.87,50.2 arc(67.79,50.17) 67.76,50.09 67.76,49.97 arc(67.65,49.87) 67.54,49.97 67.54,50.09 arc(67.51,50.17) 67.43,50.2 65.76,50.2 65,49.44 v1(65,49.37)
  BOTTOM w0.12: v1(65,49.37) 64.87,49.24 63.05,49.24 ; U2.J8 75.09,51.25 arc(75.04,51.25) 75.01,51.22 74.65,50.86 arc(74.61,50.84) 74.57,50.83 74,50.83 arc(73.93,50.86) 73.89,50.94 73.89,51.07 arc(73.78,51.18) 73.67,51.07 73.67,50.94 arc(73.64,50.86) 73.56,50.83 v1(73.09,50.83)
DDR2_CLK_B: length 15.8
  TOP w0.12: v1(72.57,51.33) 73.11,51.33 73.78,52 R1.2
  INT1 w0.12: v1(72.57,51.33) 72.56,51.32 72.56,50.95 72.21,50.61 71.07,50.61 70.9,50.44 65.59,50.44 64.93,49.78 64.83,49.78 64.7,49.65 v1(64.4,49.65)
  BOTTOM w0.12: U2.K8 74.85,52.06 74.5,51.7 73.21,51.7 72.83,51.32 72.57,51.32 v1(72.57,51.33) ; v1(64.4,49.65) 62.66,49.65 62.24,49.24
DDR2_CS_B: length 20.5
  INT1 w0.12: v1(72.01,54.01) 71.97,54.01 71.55,54.43 67.97,54.43 67.16,55.23 66.01,55.23 65.91,55.13 65.54,55.13 65.3,55.38 61.91,55.38 61.62,55.09 60.13,55.09 59.78,54.74 59.78,53.93 59.78,53.93 59.78,53.77 59.11,53.1 59.11,52.64 58.67,52.19 v1(58.67,52.01)
  BOTTOM w0.12: U2.L8 75.1,52.85 74.72,53.24 73.97,53.24 73.66,53.55 73.51,53.55 73.05,54.01 v1(72.01,54.01) ; 59.05,51.63 v1(58.67,52.01)
DDR2_D00: length 16.2
  BOTTOM w0.12: 62.24,50.84 62.25,50.84 arc(62.33,50.87) 62.37,50.94 62.37,51.19 arc(62.4,51.27) 62.48,51.3 62.7,51.3 arc(62.75,51.28) 62.77,51.22 arc(62.79,51.17) 62.85,51.15 62.91,51.15 arc(62.97,51.17) 62.99,51.22 arc(63.01,51.28) 63.07,51.3 63.32,51.3 arc(63.39,51.33) 63.42,51.4 arc(63.45,51.47) 63.52,51.5 63.54,51.5 arc(63.61,51.47) 63.64,51.4 arc(63.67,51.33) 63.74,51.3 64.92,51.3 65.11,51.11 arc(65.19,51.08) 65.27,51.11 65.54,51.38 arc(65.69,51.38) 65.69,51.23 65.42,50.96 arc(65.39,50.88) 65.42,50.8 65.58,50.65 65.66,50.65 arc(65.72,50.62) 65.74,50.56 65.74,50.54 arc(65.77,50.47) 65.84,50.44 65.86,50.44 arc(65.93,50.47) 65.96,50.54 arc(65.99,50.61) 66.06,50.65 66.08,50.65 arc(66.15,50.61) 66.18,50.54 arc(66.21,50.47) 66.28,50.44 66.3,50.44 arc(66.37,50.47) 66.4,50.54 arc(66.43,50.61) 66.5,50.65 66.73,50.65 arc(66.8,50.61) 66.84,50.53 66.84,50.05 arc(66.95,49.94) 67.06,50.05 67.06,50.53 arc(67.09,50.61) 67.17,50.65 67.39,50.65 arc(67.46,50.61) 67.5,50.53 67.5,49.51 arc(67.61,49.41) 67.72,49.51 67.72,50.53 arc(67.75,50.61) 67.83,50.65 68.05,50.65 arc(68.12,50.61) 68.16,50.53 68.16,49.75 arc(68.27,49.64) 68.38,49.75 68.38,50.53 arc(68.41,50.61) 68.48,50.65 68.7,50.65 arc(68.78,50.61) 68.81,50.53 68.81,50.19 arc(68.92,50.08) 69.03,50.19 69.03,50.53 arc(69.07,50.61) 69.14,50.65 69.37,50.65 U2.H1
DDR2_D01: length 16.3
  INT1 w0.12: v1(66.89,49.51) 66.56,49.51 65.53,48.48 64.55,48.48 arc(64.47,48.45) 64.44,48.37 64.44,48.25 arc(64.33,48.14) 64.22,48.25 64.22,48.37 arc(64.18,48.45) 64.11,48.48 64.08,48.48 63.69,48.87 63.2,48.87 arc(63.12,48.9) 63.09,48.98 63.09,49.06 arc(62.98,49.18) 62.87,49.06 62.87,48.98 arc(62.76,48.87) 62.65,48.98 62.65,49.06 arc(62.54,49.18) 62.43,49.06 62.43,48.98 arc(62.4,48.9) 62.32,48.87 62.1,48.87 arc(62.05,48.89) 62.03,48.94 arc(62.01,48.98) 61.97,49 61.88,49 arc(61.83,48.98) 61.81,48.94 arc(61.79,48.89) 61.75,48.87 61.64,48.87 61.28,49.24 60.4,49.24 60.39,49.23 60.01,49.23 59.52,49.72 v1(59.45,49.72)
  BOTTOM w0.12: v1(59.45,49.72) 59.45,49.84 59.64,50.03 U1.M13 ; v1(66.89,49.51) 66.96,49.51 67.3,49.18 arc(67.37,49.15) 67.41,49.07 67.41,48.94 arc(67.52,48.83) 67.62,48.94 67.62,49.07 arc(67.73,49.18) 67.84,49.07 67.84,48.94 arc(67.95,48.83) 68.06,48.94 68.06,49.07 arc(68.1,49.15) 68.17,49.18 68.23,49.18 arc(68.33,49.2) 68.43,49.26 68.51,49.35 68.51,49.35 arc(68.59,49.4) 68.69,49.42 arc(68.79,49.44) 68.87,49.49 68.95,49.58 arc(68.97,49.62) 68.95,49.67 arc(68.93,49.71) 68.95,49.76 69.02,49.82 arc(69.06,49.84) 69.11,49.82 arc(69.15,49.8) 69.2,49.82 69.34,49.96 69.34,49.98 69.36,50.01 arc(69.47,50.08) 69.59,50.1 69.68,50.1 arc(69.72,50.1) 69.75,50.08 69.75,50.07 arc(69.77,50.04) 69.78,50.01 69.78,49.98 arc(69.81,49.9) 69.89,49.87 69.91,49.87 arc(69.97,49.9) 70,49.96 70,50.03 arc(70.02,50.08) 70.07,50.1 70.23,50.1 arc(70.28,50.09) 70.32,50.07 arc(70.35,50.03) 70.36,49.98 U2.G2
DDR2_D02: length 16.4
  INT1 w0.12: v1(64.7,53.25) 64.45,53 64.45,52.31 64.78,51.97 v1(64.78,51.93)
  BOTTOM w0.12: v1(64.7,53.25) 64.7,53.38 64.48,53.61 64.48,53.62 63.73,54.36 62.93,54.36 62.56,53.99 62.56,53.91 62.37,53.72 62.24,53.72 61.88,53.35 61.88,53.01 arc(61.85,52.95) 61.79,52.92 arc(61.73,52.9) 61.7,52.84 61.7,52.79 arc(61.73,52.73) 61.79,52.7 arc(61.85,52.68) 61.88,52.62 61.88,52.06 61.45,51.63 61.45,51.63 ; U2.H3 71.16,50.54 arc(71.15,50.58) 71.12,50.62 70.89,50.85 arc(70.86,50.87) 70.81,50.88 68.43,50.88 arc(68.35,50.91) 68.32,50.99 68.32,51.09 arc(68.21,51.2) 68.1,51.09 68.1,50.99 arc(67.99,50.88) 67.88,50.99 67.88,51.09 arc(67.77,51.2) 67.66,51.09 67.66,50.99 arc(67.55,50.88) 67.44,50.99 67.44,51.09 arc(67.33,51.2) 67.22,51.09 67.22,50.99 arc(67.18,50.91) 67.11,50.88 66.03,50.88 arc(65.99,50.89) 65.95,50.91 arc(65.93,50.95) 65.92,51.01 65.92,51.07 arc(65.93,51.13) 65.96,51.19 65.98,51.2 arc(66.03,51.28) 66.05,51.36 66.05,51.39 arc(66.01,51.52) 65.9,51.61 65.83,51.63 arc(65.77,51.65) 65.71,51.66 65.03,51.66 64.78,51.91 v1(64.78,51.93)
DDR2_D03: length 16.3
  INT1 w0.12: v1(65.06,50.54) 65.06,50.53 64.97,50.53 64.57,50.93 arc(64.31,50.93) 64.31,50.66 64.56,50.41 arc(64.61,50.35) 64.64,50.29 arc(64.65,50.22) 64.62,50.16 arc(64.56,50.12) 64.48,50.1 64.34,50.1 arc(64.25,50.14) 64.22,50.23 64.22,50.3 arc(64.18,50.38) 64.1,50.41 63.91,50.41 arc(63.78,50.28) 63.91,50.15 63.99,50.15 arc(64.03,50.14) 64.06,50.12 64.08,50.09 arc(64.08,50.05) 64.08,50.02 64.06,49.97 arc(64.05,49.95) 64.03,49.93 64.01,49.91 arc(63.98,49.89) 63.95,49.88 63.26,49.88 arc(63.18,49.92) 63.15,49.99 63.15,50.29 arc(63.04,50.4) 62.93,50.29 62.93,49.99 arc(62.82,49.88) 62.71,49.99 62.71,50.29 arc(62.6,50.4) 62.49,50.29 62.49,49.99 arc(62.46,49.92) 62.38,49.88 62.16,49.88 62,50.05 61.99,50.05 61.42,50.05 arc(61.35,50.02) 61.32,49.96 arc(61.3,49.89) 61.23,49.87 61.2,49.87 arc(61.13,49.89) 61.1,49.96 arc(61.08,50.02) 61.01,50.05 60.98,50.05 arc(60.91,50.02) 60.88,49.96 arc(60.86,49.89) 60.79,49.87 60.76,49.87 arc(60.69,49.89) 60.66,49.96 arc(60.64,50.02) 60.57,50.05 60.41,50.05 arc(60.3,50.1) 60.25,50.21 v1(60.25,50.37)
  BOTTOM w0.12: v1(65.06,50.54) 65.06,50.53 65.1,50.53 65.43,50.21 66.14,50.21 66.47,49.88 66.47,49.34 67.22,48.59 69.28,48.59 69.54,48.85 U2.F1 ; v1(60.25,50.37) 60.25,50.64 arc(60.31,50.78) 60.45,50.84 60.64,50.84
DDR2_D04: length 16.2
  INT1 w0.12: v1(72.04,51.02) 71.17,51.02 70.82,50.67 66.21,50.67 arc(66.13,50.71) 66.1,50.78 66.1,50.79 arc(65.99,50.9) 65.88,50.79 65.88,50.78 arc(65.84,50.71) 65.77,50.67 65.55,50.67 65.23,50.99 64.85,50.99 64.61,51.22 64.12,51.22 63.7,51.64 62.5,51.64 62.11,52.03 61.63,52.03 61.26,51.65 60.67,51.65 v1(60.28,51.25)
  BOTTOM w0.12: U1.P13 59.9,51.63 v1(60.28,51.25) ; v1(72.04,51.02) 72.07,51.02 72.18,50.92 72.4,50.92 72.93,50.39 74.29,50.39 U2.H7
DDR2_D05: length 16.4
  INT1 w0.12: v1(75.56,50.82) 75.56,50.96 74.73,51.78 arc(74.7,51.86) 74.73,51.94 74.89,52.1 arc(74.89,52.25) 74.74,52.25 74.58,52.09 arc(74.42,52.09) 74.42,52.25 74.54,52.37 arc(74.54,52.52) 74.38,52.52 74.27,52.4 arc(74.19,52.37) 74.11,52.4 73.99,52.53 arc(73.95,52.55) 73.91,52.56 73.06,52.56 72.06,51.57 72,51.57 71.79,51.35 71.09,51.35 70.64,50.91 67.86,50.91 67.27,51.49 67.09,51.49 66.87,51.71 66.52,51.71 66.27,51.46 64.5,51.46 64.22,51.74 v1(64.2,51.74)
  BOTTOM w0.12: v1(64.2,51.74) 64.18,51.74 64.16,51.72 63.12,51.72 63.05,51.63 ; 75.96,50.46 75.93,50.46 75.56,50.82 v1(75.56,50.82)
DDR2_D06: length 16.3
  INT1 w0.12: v1(75.57,49.24) 75.51,49.24 75.03,48.76 71,48.76 70.78,48.53 67.12,48.53 66.76,48.18 v1(66.28,48.18)
  BOTTOM w0.12: v1(75.57,49.24) 75.96,48.85 ; v1(66.28,48.18) 65.7,48.18 65.12,48.76 61.18,48.76 60.71,49.24 60.64,49.24
DDR2_D07: length 16.2
  BOTTOM w0.12: U2.G8 74.71,49.21 72.13,49.21 71.82,48.9 arc(71.79,48.82) 71.82,48.75 72.17,48.4 arc(72.17,48.24) 72.01,48.24 71.67,48.59 arc(71.59,48.62) 71.51,48.59 71.33,48.41 70.94,48.41 70.71,48.17 70.71,47.91 70.45,47.66 69.3,47.66 69.19,47.54 68.69,47.54 68.45,47.29 67.08,47.29 66.8,47.57 66.8,48.28 65.79,49.28 arc(65.74,49.3) 65.68,49.28 arc(65.63,49.26) 65.57,49.28 65.53,49.32 arc(65.5,49.38) 65.53,49.44 arc(65.55,49.49) 65.53,49.55 65,50.08 63.09,50.08 63.05,50.03
DDR2_D08: length 15.3
  INT1 w0.12: v1(72.75,44.93) 69.73,44.93 69.58,44.77 69.58,44.47 68.92,43.81 68.15,43.81 arc(68.08,43.84) 68.05,43.91 arc(68.02,43.98) 67.95,44 67.93,44 arc(67.86,43.98) 67.83,43.91 arc(67.8,43.84) 67.73,43.81 v1(67.25,43.81)
  BOTTOM w0.12: v1(72.75,44.93) 73.1,44.93 74.28,46.1 74.76,46.1 75.11,46.46 U2.C8 ; v1(67.25,43.81) 67.19,43.81 66.45,44.55 65.02,44.55 63.85,45.71 62.76,45.71 62.43,46.03 U1.G16
DDR2_D09: length 15.2
  INT1 w0.12: v1(74.78,46.85) 74.76,46.83 74.76,46.59 74.07,45.9 72.46,45.9 72.33,46.03 71.05,46.03 70.74,46.34 65.22,46.34 64.82,45.94 64.47,45.94 64.3,46.11 62.47,46.11 62.19,46.39 61.95,46.39 v1(61.91,46.43)
  BOTTOM w0.12: 61.45,46.84 61.45,46.83 61.84,46.43 v1(61.91,46.43) ; v1(74.78,46.85) 74.76,46.85 U2.D7
DDR2_D10: length 15.3
  INT1 w0.12: v1(67.44,45.16) 66.14,45.16 65.53,44.56 64.09,44.56 arc(64.01,44.59) 63.98,44.66 63.98,44.69 arc(63.87,44.8) 63.76,44.69 63.76,44.66 arc(63.72,44.59) 63.65,44.56 63.43,44.56 62.79,45.19 61.49,45.19 61.05,45.63 60.96,45.63 v1(60.96,45.63)
  BOTTOM w0.12: v1(60.96,45.63) 60.96,45.72 U1.G14 ; U2.C2 70.05,46.46 69.7,46.81 69.05,46.81 arc(69.01,46.8) 68.97,46.77 68.62,46.42 arc(68.54,46.39) 68.47,46.42 68.14,46.75 arc(67.98,46.75) 67.98,46.6 68.31,46.27 arc(68.31,46.11) 68.16,46.11 67.83,46.44 arc(67.67,46.44) 67.67,46.28 68,45.96 arc(68,45.8) 67.84,45.8 67.52,46.13 arc(67.36,46.13) 67.36,45.97 67.69,45.64 arc(67.72,45.57) 67.69,45.49 67.47,45.27 arc(67.45,45.24) 67.44,45.2 v1(67.44,45.16)
DDR2_D11: length 15.3
  INT1 w0.12: v1(60.33,47.24) 60.76,46.81 61.39,46.81 61.43,46.85 62.04,46.85 62.14,46.95 62.85,46.95 63,46.8 63.22,46.8 arc(63.27,46.82) 63.28,46.87 arc(63.3,46.91) 63.35,46.93 63.44,46.93 arc(63.49,46.91) 63.5,46.87 arc(63.52,46.82) 63.57,46.8 63.66,46.8 arc(63.71,46.82) 63.73,46.87 arc(63.74,46.91) 63.79,46.93 63.88,46.93 arc(63.93,46.91) 63.95,46.87 arc(63.96,46.82) 64.01,46.8 64.1,46.8 arc(64.15,46.82) 64.17,46.87 arc(64.18,46.91) 64.23,46.93 64.32,46.93 arc(64.37,46.91) 64.39,46.87 arc(64.4,46.82) 64.45,46.8 64.54,46.8 arc(64.59,46.82) 64.61,46.87 arc(64.62,46.91) 64.67,46.93 64.76,46.93 arc(64.81,46.91) 64.83,46.87 arc(64.84,46.82) 64.89,46.8 65.14,46.8 arc(65.18,46.78) 65.2,46.74 65.2,46.63 arc(65.22,46.58) 65.27,46.56 70.46,46.56 v1(70.77,46.87)
  BOTTOM w0.12: U2.D3 71.31,47.41 72.23,47.41 arc(72.33,47.37) 72.37,47.27 arc(72.35,47.21) 72.32,47.16 arc(72.27,47.12) 72.21,47.11 71.73,47.11 71.49,46.87 v1(70.77,46.87) ; v1(60.33,47.24) 60.35,47.26 60.35,47.35 60.63,47.63 U1.J14
DDR2_D12: length 15.2
  INT1 w0.12: v1(60.32,46.43) 60.35,46.43 60.51,46.59 61.16,46.59 61.73,46.02 62.17,46.02 62.3,45.89 62.52,45.89 arc(62.56,45.87) 62.59,45.82 arc(62.61,45.77) 62.66,45.75 62.73,45.75 arc(62.78,45.77) 62.8,45.82 arc(62.83,45.87) 62.88,45.89 62.95,45.89 arc(63,45.87) 63.02,45.82 arc(63.05,45.77) 63.09,45.75 63.17,45.75 arc(63.22,45.77) 63.24,45.82 arc(63.27,45.87) 63.31,45.89 63.39,45.89 arc(63.44,45.87) 63.46,45.82 arc(63.49,45.77) 63.53,45.75 63.62,45.75 arc(63.66,45.77) 63.68,45.82 arc(63.71,45.87) 63.75,45.89 64.16,45.89 64.3,45.75 64.31,45.75 64.31,45.7 64.89,45.7 65.27,46.08 arc(65.31,46.11) 65.35,46.12 65.77,46.12 arc(65.85,46.08) 65.88,46 65.88,45.8 arc(65.99,45.69) 66.1,45.8 66.1,46 arc(66.14,46.08) 66.21,46.12 66.43,46.12 arc(66.51,46.08) 66.54,46.01 arc(66.57,45.93) 66.65,45.9 v1(66.81,45.9)
  BOTTOM w0.12: U2.D1 69.37,47.07 68.75,47.07 arc(68.68,47.04) 68.65,46.97 arc(68.62,46.9) 68.55,46.87 68.53,46.87 arc(68.46,46.9) 68.43,46.97 arc(68.4,47.04) 68.33,47.07 67.98,47.07 67.73,46.82 arc(67.65,46.78) 67.57,46.82 67.37,47.01 arc(67.21,47.01) 67.21,46.86 67.41,46.66 arc(67.41,46.5) 67.26,46.5 66.71,47.05 arc(66.56,47.05) 66.56,46.9 67.1,46.35 arc(67.14,46.27) 67.1,46.19 v1(66.81,45.9) ; 59.84,46.84 60.25,46.43 v1(60.32,46.43)
DDR2_D13: length 15.2
  INT1 w0.12: v1(75.58,46.86) 74.31,45.59 72.72,45.59 72.31,45.18 69.31,45.18 69.21,45.28 69.18,45.28 68.95,45.28 68.85,45.38 68.62,45.38 68.37,45.14 68.09,45.14 67.53,45.7 67.2,45.7 66.89,45.4 65.59,45.4 v1(65.41,45.58)
  BOTTOM w0.12: 63.05,46.84 63.31,46.57 arc(63.33,46.52) 63.31,46.48 arc(63.3,46.44) 63.31,46.4 63.38,46.33 arc(63.43,46.31) 63.47,46.33 arc(63.51,46.34) 63.55,46.33 63.62,46.26 arc(63.64,46.21) 63.62,46.17 arc(63.61,46.13) 63.62,46.09 63.7,46.02 arc(63.74,46) 63.78,46.02 arc(63.82,46.03) 63.86,46.02 64.3,45.58 v1(65.41,45.58) ; 75.96,47.25 75.59,46.88 75.59,46.86 v1(75.58,46.86)
